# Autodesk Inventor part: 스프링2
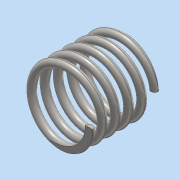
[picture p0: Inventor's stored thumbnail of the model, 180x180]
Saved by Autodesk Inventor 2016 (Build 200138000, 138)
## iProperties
Created: 2019-11
Part Number: 스프링2
Material: 스테인레스 스틸
Document SubType Name: Modeling
Designer: user
Density: 8 g/cm^3
Appearance: 반연마
Mass: 6.53089 g
Surface Area: 16.7049 cm^2
Volume: 0.816361 cm^3
Author: user
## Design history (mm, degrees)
sketch "스케치1"
  geometry: L1 (0, 0)-(8.5, 0); L2 (8.5, 0)-(8.5, -17.5); L3 (8.5, -17.5)-(0, -17.5); L4 (0, -17.5)-(0, 0); C1 r 1 at (8.5, 0)
  constraints: 8 end point, 2 parallel, 1 centre point, 1 coincident, 1 horizontal, 1 perpendicular
  dimensions: "d0" = 17 diameter of L2 L4; "d1" = 17.5 distance between parallel lines of L1 L3 (derived); "d2" = 2 diameter of C1
feature "코일1" sketch "스케치1" pitch "d3" = 10; turns "d5" = 5; dims "d4" = 17.5 (= d1), "d6" = 0, angle "d7" = 90 deg, angle "d8" = 90 deg, "d9" = 0, "d10" = 0
sketch "스케치2"
  geometry: L1 (-20, 0)-(20, 0); L2 (20, 0)-(20, -17.5); L3 (20, -17.5)-(-20, -17.5); L4 (-20, -17.5)-(-20, 0); 2 further points
  constraints: 8 end point, 2 parallel, 1 coincident, 1 horizontal, 1 midpoint, 1 perpendicular
  dimensions: "d11" = 40 distance between parallel lines of L2 L4; "d15" = 17.5 distance between parallel lines of L1 L3 (= d1)
extrude "돌출2" sketch "스케치2" stored distance "d16" = 52.5; taper "d17" = 0 deg
node "솔리드1"
